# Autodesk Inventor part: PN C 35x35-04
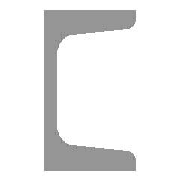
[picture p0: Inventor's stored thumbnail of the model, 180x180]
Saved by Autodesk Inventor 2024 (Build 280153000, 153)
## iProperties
Company: ATC
Created: 2023-03
Part Number: PN C 35x35-04
Material: Ogólny
Description: Ceownik
Document SubType Name: Modeling
Standard: PN-86/H-93403
Designer: Andrzej Jaskulski
Standards Organization: PN
Language: pl-PL
Size Designation: C 35x35
Categories: <MemberInstance><Categories><Category DisplayName="Kształtowniki konstrukcyjne" InternalName="089c4875-fa83-4c05-b084-43b9cc11f5ed" Mnemonic="GRDR"><CategoryPar
Stock Number: C 35x35
Density: 1 g/cm^3
Appearance: Domyślna
Checked By: A.J.
Engr Approved By: Andrzej Jaskulski
Mfg Approved By: Andrzej Jaskulski
Authority: A.J.
_CCFamilyMember: 10
_CCFamilyDisplayName: PN-86/H-93403 - Ceownik
_FrameMemberDoc: Frame Member File
_Version: 15.0.0
IsCustomPart: 1
G_L: 160,000 mm
G_W: 35,000 mm
G_H: 35,000 mm
+7DCE26F0-1766-46EF-813B-A8C94F2840FD+CUTDETAIL1: Połączenie narożne
Author: Andrzej Jaskulski
Title: A.J.: Kurs R2024-MEP
Revision Number: 1/24
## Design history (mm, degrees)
node "Płaszczyzna początkowa"
node "Płaszczyzna końcowa"
sketch "Szkic"
  geometry: L1 (0, 0)-(0, 17.5); L2 (0, 17.5)-(35, 17.5); L3 (35, 17.5)-(35, 15.47); L4 (32.239, 12.479)-(10.522, 10.742); L5 (5, 4.761)-(5, 0); L6 (5, 0)-(0, 0); L7 (20, 17.5)-(20, 11.5); L8 (35, 12.7)-(35, 11.5); L9 (35, 11.5)-(20, 11.5); L10 (0, 15)-(0, -27); L11 (-5.539, 0)-(16.007, 0); L12 (0, 0)-(0, -17.5); L13 (0, -17.5)-(35, -17.5); L14 (35, -17.5)-(35, -15.47); L15 (32.239, -12.479)-(10.522, -10.742); L16 (5, -4.761)-(5, 0); L17 (0, 26.4)-(0, -35.9) reference; L18 (-13.764, 0)-(43.809, 0) reference; A1 r 6 centre (11, 4.761) between (10.522, 10.742) and (5, 4.761); A2 r 6 centre (11, -4.761) between (5, -4.761) and (10.522, -10.742); A3 r 3 centre (32, 15.47) between (32.239, 12.479) and (35, 15.47); A4 r 3 centre (32, -15.47) between (35, -15.47) and (32.239, -12.479); 5 further points
  constraints: 32 end point, 12 point on line, 8 point on circle, 8 tangent, 6 symmetric about line, 4 centre point, 4 parallel, 3 collinear, 3 perpendicular, 2 equal radius, 5 other
  dimensions: "d0" = 5 distance between parallel lines of L1 L5 (= G_T); "d1" = 17.5 distance between parallel lines of L6 L2 (= 0.5 x G_H); "d2" = 35 distance between parallel lines of L3 L1 (= G_W); "d3" = 6 distance of L2.end L8.end (= G_T1); "d4" = 15 distance of L7.start L2.end (= G_C); "d5" = 1.2 distance of L8.start L8.end (computed from G_NG, G_C); "d23" = 6 radius of A1 (= G_IR); "d24" = 3 radius of A3 (= G_ER); "d25" = 0 distance between parallel lines of L10 L12 (computed from ex)
extrude "Bryła" new body sketch "Szkic" stored distance "d6" = 160 (= G_L); taper "d7" = 0 deg
node "Driven Length"
  sketch "Sketch3"
    geometry: L1 (0, 0)-(10, 0) reference
    constraints: 2 end point, 1 horizontal
  workplane "Work Plane3"
node "Płaszczyzna konstrukcyjna4"
feature "Podział1"
body "Solid1"
sketch "Sketch4"
  geometry: L1 (-2, 0)-(12, 0) reference; L2 (-2, 160)-(12, 160) reference
  dimensions: "d29" = 160 distance between parallel lines of L1 L2 (derived)
other parameters: "G_W" = 35 [user parameter; used in 1 equation term], "G_H" = 35 [user parameter; used in 1 equation term], "G_T" = 5 [user parameter; used in 1 equation term], "G_T1" = 6 [user parameter; used in 1 equation term], "G_NG" = 0.8 [user parameter; used in 1 equation term], "G_ER" = 3 [user parameter; used in 1 equation term], "G_IR" = 6 [user parameter; used in 1 equation term], "G_C" = 15 [user parameter; used in 2 equation terms], "G_L" = 160 (= d29) [user parameter; used in 1 equation term], "ex" = 0 [user parameter; used in 1 equation term], "G_OFFSET_START" = 0 [user parameter; used in 1 equation term], "d26" = 0 (computed from G_OFFSET_START), "d28" = 90 deg
